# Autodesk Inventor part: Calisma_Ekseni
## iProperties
Company: Autodesk, Inc.
Shininess: 64.0
Length Units: 11269
Angle Units: 11279
Time Units: 11290
Mass Units: 11283
Length Display Precision: 3
Angle Display Precision: 2
Compacted: True
Part Number: Calisma_Ekseni
Document SubType Name: Modeling
Created: 2003-11
Catalog Web Link: www.autodesk.com
Vendor: Autodesk, Inc.
Designer: Administrator
Manufacturer: Standard
Standards Organization: Custom
Density: 1 g/cm^3
Density: 0.0
Volumn: 0.0
Area: 0.0
PropertySet Name: Model Information
Control State: 0
Master: False
Checked Out: False
Author: Administrator
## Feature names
1. Extrusion1
2. Fillet1
3. Fillet2
4. Fillet3
5. Extrusion2
6. Fillet4
7. Fillet5
8. Mirror1
